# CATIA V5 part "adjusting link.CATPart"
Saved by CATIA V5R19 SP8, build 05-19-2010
Part number: adjusting link
Bounding box of the stored display mesh (mm): x 24.191 to 124.744, y 104.1 to 118.1, z -26.927 to 0.56
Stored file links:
  G:\EU_thinkMotion\CFAO_2010\MMS_groupe1\MMS_groupe1\A reprendre\gduval\CFAO kinematic ok\adjusting link.CATPart
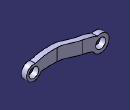
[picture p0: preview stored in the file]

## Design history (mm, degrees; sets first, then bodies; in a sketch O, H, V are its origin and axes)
Body1 (main body)
  Plane1: stored without definition
  Plane2: stored without definition
  Point1 to Point4: stored without definition
  Line1: type PtPt, FirstPoint Point1, SecondPoint Point2
  Line2: type PtPt, FirstPoint Point2, SecondPoint Point3
  Line3: type PtPt, FirstPoint Point4, SecondPoint Point3
  Sketch1 on xy-plane, origin (0, 0, 0), H (1, 0, 0), V (0, 1, 0)
    line L1 (131.0921, 111.1) -> (84.7886, 111.1)
    point P2 (84.7886, 111.1)
    spline S1 through (84.7886, 111.1) (73.1051, 113.8449) (66.9143, 116.624) (59.0114, 118.1)
    line L2 (59.0114, 118.1) -> (26.8351, 118.1)
    point P3 (59.0114, 118.1)
    point P4 (26.8351, 118.1)
    reference projected line E1 (35.202, 118.1) -> (51.291, 118.1) from Line3
    point P6 (59.0114, 111.1)
    line L3 (59.0114, 111.1) -> (26.8351, 111.1)
    spline S2 through (84.7886, 104.1) (73.1051, 106.8449) (66.9143, 109.624) (59.0114, 111.1)
    point P7 (84.7886, 104.1)
    point P8 (131.0921, 104.1)
    line L4 (131.0921, 104.1) -> (84.7886, 104.1)
    line L5 (131.0921, 111.1) -> (131.0921, 104.1)
    point P9 (131.0921, 104.1)
    reference projected line E2 (115.24, 104.1) -> (64.197, 104.1) from Line1
    reference projected line E3 (115.24, 104.1) -> (64.197, 104.1) from Line1
    line L6 (26.8351, 118.1) -> (26.8351, 111.1)
    point P10 (84.7886, 111.1)
    point P11 (59.0114, 118.1)
    point P12 (73.1051, 113.8449)
    point P13 (73.1051, 106.8449)
    point P14 (66.9143, 116.624)
    point P15 (66.9143, 109.624)
    point P16 (59.0114, 111.1)
    point P17 (84.7886, 104.1)
    distance L3 L2 = 7
    distance P13 P12 V = 7
    distance P14 P15 V = 7
    distance P11 P16 H = 0
    distance L1 L4 = 7
    distance P15 P14 H = 0
    distance P13 P12 H = 0
    coincidence: P11 P3, L2 E1, P8 P9, P16 P6, P17 P7, L4 E2, P10 P2
    tangency: S1 L1, S1 L2, S2 E3
    fix: P4
    vertical: L5 V, L6 V
    horizontal: L2 H, L1 H
  Pad1: profile Sketch1, direction (0, 0, -1), length 25, opposite side length 1
  Sketch2 on face of Pad1 from Sketch1.L4, origin (0, 104.1, 0), H (1, 0, 0), V (0, 0, 1)
    arc A1 centre (35.202, -16.01) radius 8.2 from (36.5591, -7.9231) to (40.2919, -22.4391) ccw
    point P1 (35.202, -16.01)
    point P2 (36.5591, -7.9231)
    point P3 (40.2919, -22.4391)
    reference projected point E1 (35.202, -16.01) from Point4
    spline S1 through (40.2919, -22.4391) (47.8905, -19.5804) (63.7654, -16.01) (83.3214, -15.324) (101.957, -15.324) (106.2137, -15.7841)
    spline S2 through (113.4677, -3.088) (102.8777, -0.484) (93.0997, 0.5595) (72.5084, 0.3294) (61.8102, 0) (47.7759, -2.8916) (42.4842, -4.6172) (36.5591, -7.9231)
    arc A2 centre (115.24, -12.521) radius 9.598 from (106.2137, -15.7841) to (113.4677, -3.088) ccw
    point P4 (113.4677, -3.088)
    point P5 (115.24, -12.521)
    point P6 (106.2137, -15.7841)
    reference projected point E2 (115.24, -12.521) from Point1
    point P7 (40.2919, -22.4391)
    point P10 (36.5591, -7.9231)
    point P11 (113.4677, -3.088)
    point P12 (106.2137, -15.7841)
    radius A1 = 8.2
    coincidence: E1 P1, P7 P3, P10 P2, P11 P4, P6 P12, P5 E2
  Pocket1: profile Sketch2, direction (0, 1, 0), through (limit type 6), outer side
  Line4: type PtDir, RefPoint Point4, Direction Plane2, Start -20, End 20
  Line5: type Normal, RefPoint Point1, RefSkin Plane1, Start -20, End 20
  Sketch3 on face of Pad1 from Sketch1.L3, origin (0, 111.1, 0), H (1, 0, 0), V (0, 0, 1)
    circle A1 centre (35.202, -16.01) radius 11.0112
    point P1 (35.202, -16.01)
    reference projected point E1 (35.202, -16.01) from Line4
    coincidence: P1 E1
  Pad2: profile Sketch3, direction (0, 1, 0), up to face of Pad1 from Sketch1.L2
  Sketch4 on face of Pad1, origin (35.202, 111.1, -16.01), H (1, 0, 0), V (0, 0, 1)
    point P1 (0, 0)
    intersected point E1 (0, 0) from Line4
    coincidence: E1 P1
  Hole1: placed by Sketch4, at (35.202, 111.1, -16.01) direction (0, 1, 0), diameter 13, through (limit type 6)
  Sketch5 on face of Pad1 from Sketch1.L4, origin (115.24, 104.1, -12.521), H (1, 0, 0), V (0, 0, 1)
    point P1 (0, 0)
    intersected point E1 (0, 0) from Line5
    coincidence: E1 P1
  Hole2: placed by Sketch5, at (115.24, 104.1, -12.521) direction (0, 1, 0), diameter 13, through (limit type 6)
